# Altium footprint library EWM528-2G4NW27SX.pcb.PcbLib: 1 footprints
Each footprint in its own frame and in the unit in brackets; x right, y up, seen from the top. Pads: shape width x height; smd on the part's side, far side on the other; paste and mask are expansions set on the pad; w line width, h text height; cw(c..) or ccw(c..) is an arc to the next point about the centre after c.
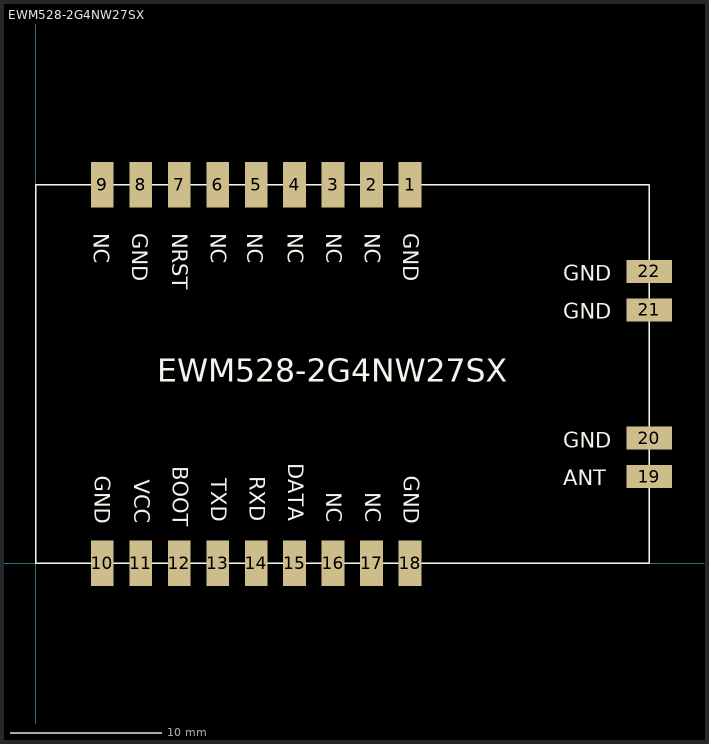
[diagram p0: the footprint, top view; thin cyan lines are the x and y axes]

## EWM528-2G4NW27SX [mm]
pads (22):
  rect 1.5x3 smd: 1(24.7,25) 2(22.16,25) 3(19.62,25) 4(17.08,25) 5(14.54,25) 6(12,25) 7(9.46,25) 8(6.92,25) 9(4.38,25) 10(4.38,0) 11(6.92,0) 12(9.46,0) 13(12,0) 14(14.54,0) 15(17.08,0) 16(19.62,0) 17(22.16,0) 18(24.7,0)
  rect 3x1.5 smd: 19(40.5,5.73) 20(40.5,8.27) 21(40.5,16.73) 22(40.5,19.27)
Top Overlay:
  lines w0.1: 0,0 40.5,0 40.5,25 0,25 0,0
  text "EWM528-2G4NW27SX" at 8,12 h1.52
  text "DATA" at 16.66,6.609 h1
  text "VCC" at 6.49,5.524 h1
  text "BOOT" at 9.04,6.424 h1
  text "NC" at 19.17,4.71 h1
  text "GND" at 3.9,5.79 h1
  text "TXD" at 11.58,5.619 h1
  text "RXD" at 14.11,5.748 h1
  text "NC" at 21.736,4.71 h1
  text "GND" at 24.273,5.79 h1
  text "GND" at 6.35,21.786 h1
  text "NRST" at 9.017,21.786 h1
  text "NC" at 16.637,21.786 h1
  text "NC" at 19.177,21.786 h1
  text "NC" at 3.81,21.786 h1
  text "NC" at 13.97,21.786 h1
  text "NC" at 11.557,21.786 h1
  text "NC" at 21.717,21.786 h1
  text "GND" at 24.257,21.786 h1
  text "GND" at 34.819,18.664 h1
  text "GND" at 34.819,16.145 h1
  text "ANT" at 34.819,5.145 h1
  text "GND" at 34.819,7.645 h1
